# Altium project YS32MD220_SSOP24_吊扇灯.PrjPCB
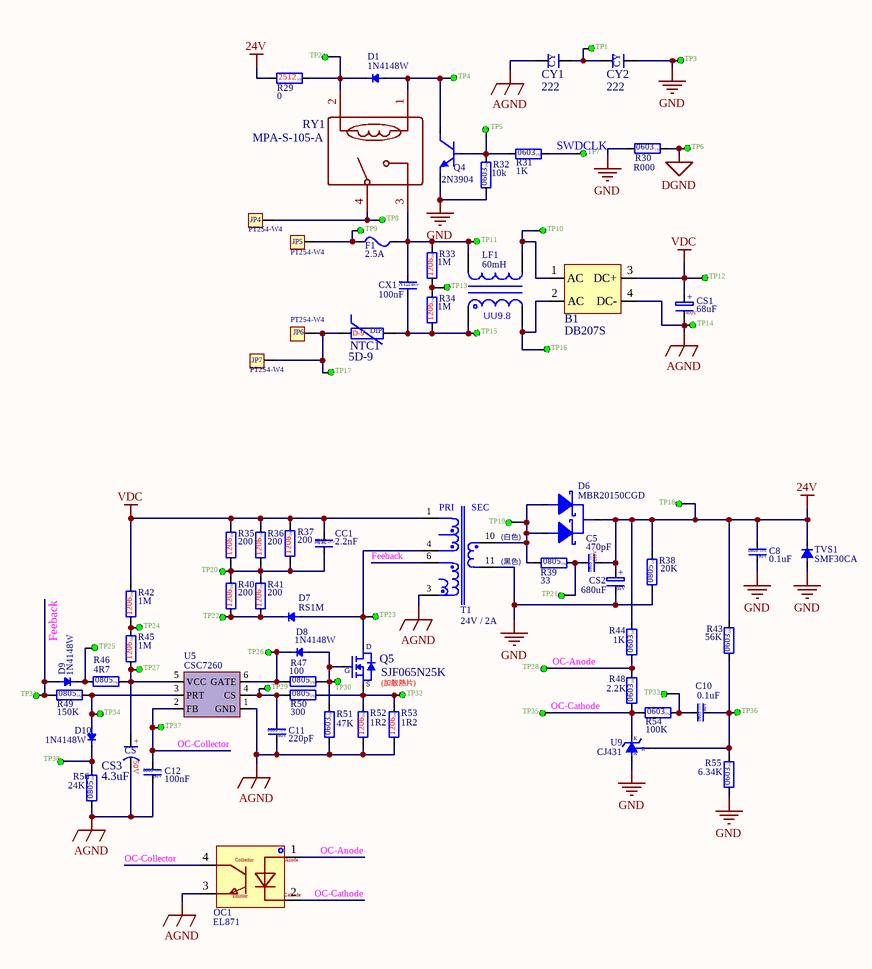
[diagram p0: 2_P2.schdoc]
2 sheets, 168 parts. Net scope: flat (ports and power ports of the same name join across sheets).
Board file: 吊扇灯_DEMO.pcbdoc
Sheets:
  2_P2.schdoc
  1_1.schdoc

## Sheet 2_P2.schdoc
size 307 x 218 mm; Symbol: Drawing-Symbol_A4; Device: Drawing-Symbol_A4; Company: 嘉立创EDA; Version: V1.0; Page Size: A4; @Project Name: YS32MD220_Demo_SSOP24_V1_0; @Page Count: 2; @Update Date: 2025-12-08; @Create Date: 2025-12-08; @Schematic Name: 吊扇灯_DEMO; @Page No: 2; @Page Name: P2; @Board Name: YS32MD220_FAN_LED_Demo_V1_0; @Create Time: 07:20:52; @Update Time: 15:23:17; Title Block Position: 3; Size: A4; Width: 1170; Height: 825; Region Start: 1; X Region Count: 6; Y Region Count: 4; Blade Width: 10

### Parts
B1  DB207S  [DBS]
C5  470pF  [C 0805]
C8  0.1uF  [C 0805]
C10  0.1uF  [C 0603]
C11  220pF  [C 0603]
C12  100nF  [C 0603]
CC1  2.2nF  [CC 5*5]
CS1  68uF  [CAP 7.5*18*35.5 - BK]
CS2  680uF  [CAP 5.0*10*16 - GD]
CS3  4.3uF  [CAP 2.5*5*11 - BK]
CX1  100nF  [CX 10*13*11]
CY1  222  [CY 5*7*2.5]
CY2  222  [CY 5*7*2.5]
D1  1N4148W  [SOD-123]
D6  MBR20150CGD  [TO263-2]
D7  RS1M  [SMA]
D8  1N4148W  [SOD-123]
D9  1N4148W  [SOD-123]
D10  1N4148W  [SOD-123]
F1  2.5A  [FU DIP 8.5X8.5X4]
JP4  PT254-W4  [PT254-W4]
JP5  PT254-W4  [PT254-W4]
JP6  PT254-W4  [PT254-W4]
JP7  PT254-W4  [PT254-W4]
LF1  60mH  [UU9.8]
NTC1  5D-9  [NTC D-9]
OC1  EL871  [DIP-4]
Q4  2N3904  [SOT23-3]
Q5  SJF065N25K  [TO220F-A(Heat sinks)]
R29  0  [R 2512]
R30  R000  [R 0603-HP]
R31  1K  [R 0603]
R32  10k  [R 0603]
R33  1M  [R 1206]
R34  1M  [R 1206]
R35  200  [R 1206]
R36  200  [R 1206]
R37  200  [R 1206]
R38  20K  [R 0805]
R39  33  [R 0805]
R40  200  [R 1206]
R41  200  [R 1206]
R42  1M  [R 1206]
R43  56K  [R 0603]
R44  1K  [R 0603]
R45  1M  [R 1206]
R46  4R7  [R 0805]
R47  100  [R 0805]
R48  2.2K  [R 0603]
R49  150K  [R 0805]
R50  300  [R 0805]
R51  47K  [R 0603]
R52  1R2  [R 1206]
R53  1R2  [R 1206]
R54  100K  [R 0603]
R55  6.34K  [R 0603]
R56  24K  [R 0805]
RY1  MPA-S-105-A  [MPA-S-105-A]
T1  24V / 2A  [ZZ200113]
TP1  TP  [TP_circle_1.0mm]  (value not drawn)
TP2  TP  [TP_circle_1.0mm]  (value not drawn)
TP3  TP  [TP_circle_1.0mm]  (value not drawn)
TP4  TP  [TP_circle_1.0mm]  (value not drawn)
TP5  TP  [TP_circle_1.0mm]  (value not drawn)
TP6  TP  [TP_circle_1.0mm]  (value not drawn)
TP7  TP  [TP_circle_1.0mm]  (value not drawn)
TP8  TP  [TP_circle_1.0mm]  (value not drawn)
TP9  TP  [TP_circle_1.0mm]  (value not drawn)
TP10  TP  [TP_circle_1.0mm]  (value not drawn)
TP11  TP  [TP_circle_1.0mm]  (value not drawn)
TP12  TP  [TP_circle_1.0mm]  (value not drawn)
TP13  TP  [TP_circle_1.0mm]  (value not drawn)
TP14  TP  [TP_circle_1.0mm]  (value not drawn)
TP15  TP  [TP_circle_1.0mm]  (value not drawn)
TP16  TP  [TP_circle_1.0mm]  (value not drawn)
TP17  TP  [TP_circle_1.0mm]  (value not drawn)
TP18  TP  [TP_circle_1.0mm]  (value not drawn)
TP19  TP  [TP_circle_1.0mm]  (value not drawn)
TP20  TP  [TP_circle_1.0mm]  (value not drawn)
TP21  TP  [TP_circle_1.0mm]  (value not drawn)
TP22  TP  [TP_circle_1.0mm]  (value not drawn)
TP23  TP  [TP_circle_1.0mm]  (value not drawn)
TP24  TP  [TP_circle_1.0mm]  (value not drawn)
TP25  TP  [TP_circle_1.0mm]  (value not drawn)
TP26  TP  [TP_circle_1.0mm]  (value not drawn)
TP27  TP  [TP_circle_1.0mm]  (value not drawn)
TP28  TP  [TP_circle_1.0mm]  (value not drawn)
TP29  TP  [TP_circle_1.0mm]  (value not drawn)
TP30  TP  [TP_circle_1.0mm]  (value not drawn)
TP31  TP  [TP_circle_1.0mm]  (value not drawn)
TP32  TP  [TP_circle_1.0mm]  (value not drawn)
TP33  TP  [TP_circle_1.0mm]  (value not drawn)
TP34  TP  [TP_circle_1.0mm]  (value not drawn)
TP35  TP  [TP_circle_1.0mm]  (value not drawn)
TP36  TP  [TP_circle_1.0mm]  (value not drawn)
TP37  TP  [TP_circle_1.0mm]  (value not drawn)
TP38  TP  [TP_circle_1.0mm]  (value not drawn)
TVS1  SMF30CA  [SOD-123]
U5  CSC7260  [SOT23-6]
U9  CJ431  [SOT23-3]

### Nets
24V: C5.2 C8.1 CS2.1 D6.2(K) R29.1 R38.2 R43.2 R44.2 TP18.1 TVS1.2
AGND: B1.4(DC-) C11.2 C12.2 CS1.2 CS3.2(K) CY1.2 OC1.3 R51.1 R52.1 R53.1 R56.1 T1.3 TP14.1 U5.1(GND)
DGND: R30.2 TP6.1
GND: C8.2 CS2.2 CY2.1 Q4.2(E) R30.1 R32.1 R38.1 R55.1 T1.11 TP3.1 TVS1.1 U9.2(A)
VDC: B1.3(DC+) CC1.1 CS1.1 R35.2 R36.2 R37.2 R42.2 T1.1 TP12.1
Feeback: D9.1(A) R49.1 T1.6 TP31.1
OC-Anode: OC1.1 R44.1 R48.2 TP28.1
OC-Cathode: OC1.2 R48.1 R54.1 TP35.1 U9.1(K)
OC-Collector: C12.1 OC1.4 TP37.1 U5.2(FB)
SWDCLK: R31.2 TP7.1
NetB1_1: B1.1(AC) LF1.3 TP10.1
NetB1_2: B1.2(AC) LF1.2 TP16.1
NetC5_1: C5.1 R39.2 TP21.1
NetC10_1: C10.1 R54.2 TP33.1
NetC10_2: C10.2 R43.1 R55.2 TP36.1 U9.3(R)
NetC11_1: C11.1 R50.1 TP29.1 U5.4(CS)
NetCC1_2: CC1.2 R35.1 R36.1 R37.1 R40.2 R41.2 TP20.1
NetCS3_1: CS3.1(A) R45.1 R46.2 TP27.1 U5.5(VCC)
NetCX1_1: CX1.1 LF1.1 NTC1.2 R34.1 TP15.1
NetCX1_2: CX1.2 F1.2 LF1.4 R33.2 RY1.3 TP11.1
NetCY1_1: CY1.1 CY2.2 TP1.1
NetD1_1: D1.1(A) Q4.3(C) RY1.1 TP4.1
NetD1_2: D1.2(K) R29.2 RY1.2 TP2.1
NetD6_1: D6.1(A) D6.3(A) R39.1 T1.10 TP19.1
NetD7_1: D7.1(A) Q5.2(D) T1.4 TP23.1
NetD7_2: D7.2(K) R40.1 R41.1 TP22.1
NetD8_1: D8.1(A) Q5.1(G) R47.2 R51.2 TP30.1
NetD8_2: D8.2(K) R47.1 TP26.1 U5.6(GATE)
NetD9_2: D9.2(K) R46.1 TP25.1
NetD10_1: D10.1(A) R49.2 TP34.1 U5.3(PRT)
NetD10_2: D10.2(K) R56.2 TP38.1
NetF1_1: F1.1 JP5.1(PT254-W4) TP9.1
NetJP4_1: JP4.1(PT254-W4) RY1.4 TP8.1
NetJP6_1: JP6.1(PT254-W4) JP7.1(PT254-W4) NTC1.1 TP17.1
NetQ4_1: Q4.1(B) R31.1 R32.2 TP5.1
NetQ5_3: Q5.3(S) R50.2 R52.2 R53.2 TP32.1
NetR33_1: R33.1 R34.2 TP13.1
NetR42_1: R42.1 R45.2 TP24.1

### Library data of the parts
B1 = DB207S: 1000V/2A整流桥
C5 = C_0805_10%_200V: 電容 0805 10% 200V
C8 = C_0805_10%_50V: 電容 0805 10% 50V
C10-C12 = C_0603_10%_50V: 電容 0603 10% 50V
CC1 = CC_DIP_1KV: 陶瓷電容 DIP IKV 腳距5mm
CS1 = CS_DIP_400V: 電解電容 DIP 400V
CS2 = CS_35V: 電解電容 SMD 35V
CS3 = CS_50V: 直插固态电容
CX1 = CX1_2.5KV: X1電容 ≥2.5KV
CY1 CY2 = CY: 安规Y电容; BOM名称: 高压陶瓷电容，Y电容; 版权归属: 封装库来自淘宝 ID：黄晶宝石
D1 D8-D10 = 1N4148: 开关二极管 1N4148W
D6 = MBR20150CGD: 肖特基二极管
D7 = RS1M: 快恢復二級管 / RS1M
F1 = Fuse: 保險絲
JP4-JP7 = PT254-W4: BOM名称: 电话接口; 版权归属: 封装库来自淘宝 ID：黄晶宝石
LF1 = L-UU 9.8: 共模电感 UU9.8
NTC1 = RT_NTC_D-9: DIP NTC (XD-9); BOM名称: 压敏电阻; 版权归属: 封装库来自淘宝 ID：黄晶宝石
OC1 = EL817: 亿光(EVERLIGHT)
Q4 = 2N3904_SMD: SMD NPN 2N3904; BOM名称: 高频放大-NPN型; 版权归属: 封装库来自淘宝 ID：黄晶宝石; 属性: 40V 1.5A 1W 100MHZ
Q5 = MOS_SJF065N25K(散熱): 無錫商甲導體 / SJF065N25K / 680V 4A / (需要安裝散色片)
R29 = R_2512_5%: 貼片電阻 2512 5% 1w
R30 = R_0603_1%: 貼片電阻 0603 1%
R31 R32 R43 R44 R48 R51 R54 R55 = R_0603_5%: 電阻 0603 5%
R33-R37 R40-R42 R45 R52 R53 = R_1206_5%: 電阻 1206 5%
R38 R39 R46 R47 R49 R50 R56 = R_0805_5%: 電阻 0805 5%
RY1 = MPA-S-105-A: MPA-S-105-A / 5V
T1 = ZZ200113: 廣東中正電子
TP1-TP38 = ICT_TP_1.0mm: ICT測試點 1.0mm
TVS1 = SMF30CA: TVS 30V 4A 200W
U5 = CSC7260_1: 晶源微 PWM IC

## Sheet 1_1.schdoc
size 307 x 218 mm; Symbol: Altium_A2; Device: Altium_A2; SheetNumber: 0; SheetTotal: 0; PageSetup: Record=PageOptions聨CenterHorizontal=True聨CenterVertical=True聨PrintScale=0.73聨XCorrection=1.00聨YCorrection=1.00聨PrintKind=0聨BorderSize=5000000聨LeftOffset=0聨BottomOffset=0聨Orientation=2聨PaperLength=1000聨PaperWidth=1000聨Scale=100聨PaperSource=7聨PrintQuality=-4聨MediaType=1聨DitherType=10聨PaperKind=A3聨PrintScaleMode=1; Width: 1170; Height: 825; X Region Count: 0; Y Region Count: 0; Blade Width: 0; Region Start: 1; Title Block Position: 3; @Page No: 1; @Page Count: 2; @Schematic Name: 吊扇灯_DEMO; @Project Name: 吊扇灯_DEMO_V1; @Board Name: 吊扇灯_DEMO; @Update Date: 2025-12-09; @Create Time: 06:26:14; @Update Time: 13:44:14; @Page Name: 1; @Create Date: 2025-12-05
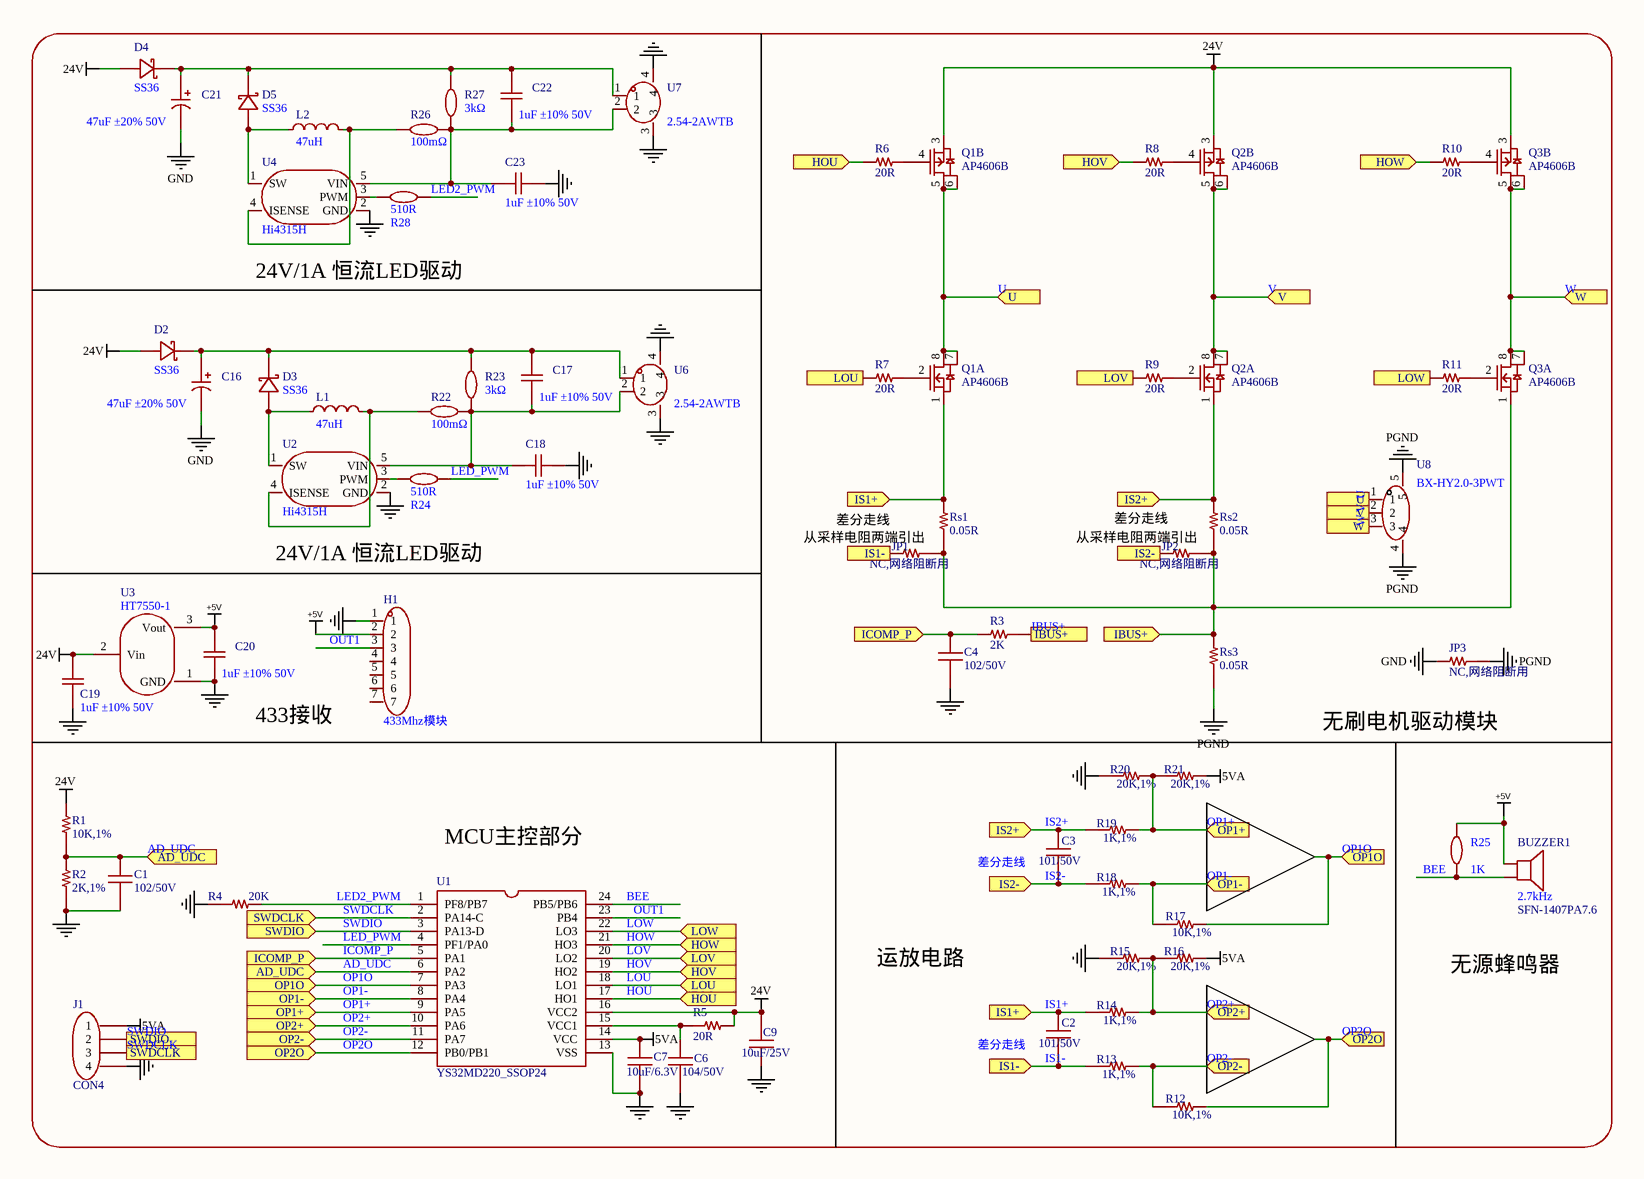
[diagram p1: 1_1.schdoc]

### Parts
BUZZER1  2.7kHz  [BUZ-TH_BD14.0-P7.60-D0.7]
C1  102/50V  [C0603]
C2  101/50V  [C0603]
C3  101/50V  [C0603]
C4  102/50V  [C0603]
C6  104/50V  [C0603]
C7  10uF/6.3V  [C0603]
C9  10uF/25V  [C0805]
C16  47uF ±20% 50V  [CAP-SMD_BD6.3-L6.6-W6.6-FD]
C17  1uF ±10% 50V  [C0603]
C18  1uF ±10% 50V  [C0603]
C19  1uF ±10% 50V  [C0603]
C20  1uF ±10% 50V  [C0603]
C21  47uF ±20% 50V  [CAP-SMD_BD6.3-L6.6-W6.6-FD]
C22  1uF ±10% 50V  [C0603]
C23  1uF ±10% 50V  [C0603]
D2  SS36  [SMA_L4.3-W2.6-LS5.0-FD]
D3  SS36  [SMA_L4.3-W2.6-LS5.0-FD]
D4  SS36  [SMA_L4.3-W2.6-LS5.0-FD]
D5  SS36  [SMA_L4.3-W2.6-LS5.0-FD]
H1  433Mhz模块  [433Mhz]
J1  CON4  [SIP4-2.0]
JP1  NC,网络阻断用  [JP3.0]
JP2  NC,网络阻断用  [JP3.0]
JP3  NC,网络阻断用  [JP3.0]
L1  47uH  [IND-SMD_L12.3-W12.3]
L2  47uH  [IND-SMD_L12.3-W12.3]
Q1  AP4606B  [SOP8]  (parts A,B of 2)
Q2  AP4606B  [SOP8]  (parts A,B of 2)
Q3  AP4606B  [SOP8]  (parts A,B of 2)
R1  10K,1%  [R0603]
R2  2K,1%  [R0603]
R3  2K  [R0603]
R4  20K  [R0603]
R5  20R  [R0603]
R6  20R  [R0603]
R7  20R  [R0603]
R8  20R  [R0603]
R9  20R  [R0603]
R10  20R  [R0603]
R11  20R  [R0603]
R12  10K,1%  [R0603]
R13  1K,1%  [R0603]
R14  1K,1%  [R0603]
R15  20K,1%  [R0603]
R16  20K,1%  [R0603]
R17  10K,1%  [R0603]
R18  1K,1%  [R0603]
R19  1K,1%  [R0603]
R20  20K,1%  [R0603]
R21  20K,1%  [R0603]
R22  100mΩ  [R0805]
R23  3kΩ  [R0805]
R24  510R  [R0603]
R25  1K  [R0603]
R26  100mΩ  [R0805]
R27  3kΩ  [R0805]
R28  510R  [R0603]
Rs1  0.05R  [R1206]
Rs2  0.05R  [R1206]
Rs3  0.05R  [R1206]
U1  YS32MD220_SSOP24  [SSOP-24_L8.7-W3.9-P0.635]
U2  Hi4315H  [SOT-89-5_L4.5-W2.5-P1.50-LS4.5-TL]
U3  HT7550-1  [SOT-89-3_L4.5-W2.5-P1.50-LS4.2-BR]
U4  Hi4315H  [SOT-89-5_L4.5-W2.5-P1.50-LS4.5-TL]
U6  2.54-2AWTB  [CONN-SMD_2P-P2.54_XH2.54-2AWT]
U7  2.54-2AWTB  [CONN-SMD_2P-P2.54_XH2.54-2AWT]
U8  BX-HY2.0-3PWT  [CONN-SMD_3P-P2.0_BX-HY2.0-3PWT]

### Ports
AD_UDC (in), HOU (in), HOV (in), HOW (in), IBUS+ (in), ICOMP_P (in), IS1+ (in), IS1- (in), IS2+ (in), IS2- (in), LOU (in), LOV (in), LOW (in), OP1+ (in), OP1- (in), OP1O (in), OP2+ (in), OP2- (in), OP2O (in), SWDCLK (in), SWDIO (in), U (in), V (in), W (in)

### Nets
5VA: C7.1 J1.1 R16.1 R21.1 U1.14(VCC)
24V: C9.2 C19.2 D2.1(A) D4.1(A) Q1.3(S) Q2.3(S) Q3.3(S) R1.1 R5.1 U1.16(VCC2) U3.2(Vin)
+5V: BUZZER1.1 C20.2 H1.2 R25.2 U3.3(Vout)
GND: C1.2 C4.2 C6.2 C7.2 C9.1 C16.2 C18.1 C19.1 C20.1 C21.2 C23.1 H1.1 J1.4 JP3.1 R2.2 R4.2 R15.2 R20.2 U1.13(VSS) U2.2(GND) U3.1(GND) U4.2(GND) U6.3 U6.4 U7.3 U7.4
PGND: JP3.2 Rs3.2 U8.4 U8.5
AD_UDC: C1.1 R1.2 R2.1 U1.6(PA2) ; port AD_UDC
BEE: BUZZER1.2 R25.1 U1.24(PB5/PB6)
HOU: R6.1 U1.17(HO1) ; port HOU
HOV: R8.1 U1.19(HO2) ; port HOV
HOW: R10.1 U1.21(HO3) ; port HOW
IBUS+: JP1.2 JP2.2 Q3.1(G) R3.2 Rs1.2 Rs2.2 Rs3.1 ; port IBUS+
ICOMP_P: C4.1 R3.1 U1.5(PA1) ; port ICOMP_P
IS1+: C2.1 Q1.1(G) R14.2 Rs1.1 ; port IS1+
IS1-: C2.2 JP1.1 R13.2 ; port IS1-
IS2+: C3.1 Q2.1(G) R19.2 Rs2.1 ; port IS2+
IS2-: C3.2 JP2.1 R18.2 ; port IS2-
LED2_PWM: R4.1 R28.2 U1.1(PF8/PB7)
LED_PWM: R24.2 U1.4(PF1/PA0)
LOU: R7.1 U1.18(LO1) ; port LOU
LOV: R9.1 U1.20(LO2) ; port LOV
LOW: R11.1 U1.22(LO3) ; port LOW
OP1+: R19.1 R20.1 R21.2 U1.9(PA5) ; port OP1+
OP1-: R17.2 R18.1 U1.8(PA4) ; port OP1-
OP1O: R17.1 U1.7(PA3) ; port OP1O
OP2+: R14.1 R15.1 R16.2 U1.10(PA6) ; port OP2+
OP2-: R12.2 R13.1 U1.11(PA7) ; port OP2-
OP2O: R12.1 U1.12(PB0/PB1) ; port OP2O
OUT1: H1.3 U1.23(PB4)
SWDCLK: J1.3 U1.2(PA14-C) ; port SWDCLK
SWDIO: J1.2 U1.3(PA13-D) ; port SWDIO
U: Q1.5(D) Q1.6(D) Q1.7(D) Q1.8(D) U8.1 ; port U
V: Q2.5(D) Q2.6(D) Q2.7(D) Q2.8(D) U8.2 ; port V
W: Q3.5(D) Q3.6(D) Q3.7(D) Q3.8(D) U8.3 ; port W
NetC6_1: C6.1 R5.2 U1.15(VCC1)
NetC16_1: C16.1 C17.2 D2.2(K) D3.2(K) R23.2 U6.1
NetC17_1: C17.1 C18.2 R22.2 R23.1 U2.5(VIN) U6.2
NetC21_1: C21.1 C22.2 D4.2(K) D5.2(K) R27.2 U7.1
NetC22_1: C22.1 C23.2 R26.2 R27.1 U4.5(VIN) U7.2
NetD3_1: D3.1(A) L1.1 U2.1(SW)
NetD5_1: D5.1(A) L2.1 U4.1(SW)
NetL1_2: L1.2 R22.1 U2.4(ISENSE)
NetL2_2: L2.2 R26.1 U4.4(ISENSE)
NetQ1_2: Q1.2(S) R7.2
NetQ1_4: Q1.4(G) R6.2
NetQ2_2: Q2.2(S) R9.2
NetQ2_4: Q2.4(G) R8.2
NetQ3_2: Q3.2(S) R11.2
NetQ3_4: Q3.4(G) R10.2
NetR24_1: R24.1 U2.3(PWM)
NetR28_1: R28.1 U4.3(PWM)

Not connected (* = marked no-connect by the designer): H1 4 5 6 7

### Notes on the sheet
- 24V/1A 恒流LED驱动
- (near JP1) 差分走线
- (near JP2) 差分走线
- (near JP1) 从采样电阻两端引出
- (near JP2) 从采样电阻两端引出
- 433接收
- 无刷电机驱动模块
- MCU主控部分
- 差分走线
- 运放电路
- 无源蜂鸣器

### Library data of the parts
BUZZER1 = SFN-1407PA7.6: Manufacturer: S&S(海旭); Add into BOM: yes; Driver Circuitry: 无源(外部驱动); Sound Pressure Level(SPL): 85dB
C1 C4 = 102/50V: Symbol: CAP; Origin Footprint 2: C0805; Origin Footprint 3: C1206; Origin Footprint 4: C0402; Add into BOM: yes
C2 C3 = 101/50V: Symbol: CAP; Origin Footprint 2: C0805; Origin Footprint 3: C1206; Origin Footprint 4: C0402; Add into BOM: yes
C6 = 104/50V: Symbol: CAP; Origin Footprint 2: C0805; Origin Footprint 3: C1206; Origin Footprint 4: C0402; Origin Footprint 5: 0603; Add into BOM: yes
C7 = 10uF/6.3V: Symbol: CAP; Origin Footprint 2: C0805; Origin Footprint 3: C1206; Origin Footprint 4: C0402; Add into BOM: yes
C9 = 10uF/25V: Symbol: CAP; Origin Footprint 2: C0603; Origin Footprint 3: C1206; Origin Footprint 4: C0402; Add into BOM: yes
C16 C21 = JVJ50V47M6x8: Manufacturer: JIERR(捷而瑞); Add into BOM: yes; Ripple Current: 63mA@120Hz; Lifetime: 2000hrs@105℃
C17-C20 C22 C23 = CL10A105KB8NNNC: Manufacturer: SAMSUNG(三星); Add into BOM: yes; Temperature Coefficient: X5R
D2-D5 = SS36_C7420367: Manufacturer: R+O(宏嘉诚); Add into BOM: yes; Diode Configuration: 独立式; Voltage - Forward(Vf@If): 700mV@3.0A; Voltage - DC Reverse(Vr): 60V; Current - Rectified: 3A; Reverse Leakage Current (Ir): 10mA@60V; Operating Junction Temperature Range: -55℃~+150℃; Non-Repetitive Peak Forward Surge Current: 80A
H1 = PM254V-11-07-H85: Manufacturer: XFCN(兴飞); Add into BOM: yes
J1 = CON4: Origin Footprint 2: SIP4; Add into BOM: yes
JP1 JP2 = NC,网络阻断用: Symbol: RES; Origin Footprint 2: R0402; Origin Footprint 3: R0603; Origin Footprint 4: R0805; Origin Footprint 5: R1206; Origin Footprint 6: R2010; Origin Footprint 7: R2512; Add into BOM: yes; Origin Footprint 1: JP1.0
JP3 = NC,网络阻断用: Symbol: RES; Origin Footprint 2: R0402; Origin Footprint 3: R0603; Origin Footprint 4: R0805; Origin Footprint 5: R1206; Origin Footprint 6: R2010; Origin Footprint 7: R2512; Add into BOM: yes
L1 L2 = SMDRI127-470MT: Manufacturer: SXN(顺翔诺); Add into BOM: yes; Tolerance: ±20%; Current Rating: 2.5A; Current - Saturation(Isat): 4.6A; DC Resistance(DCR): 100mΩ; Type: 屏蔽电感
Q1-Q3 = AP4606B: Symbol: MOS-PN-8; Origin Footprint 2: DFN3x3D; Origin Footprint 3: DFN5X6D; Add into BOM: yes
R1 R12 R17 = 10K,1%: Symbol: RES; Origin Footprint 2: R0402; Origin Footprint 3: R0805; Origin Footprint 4: R1206; Origin Footprint 5: R2010; Origin Footprint 6: R2512; Add into BOM: yes
R2 = 2K,1%: Symbol: RES; Origin Footprint 2: R0402; Origin Footprint 3: R0805; Origin Footprint 4: R1206; Origin Footprint 5: R2010; Origin Footprint 6: R2512; Add into BOM: yes
R3 = 2K: Symbol: RES; Origin Footprint 2: R0402; Origin Footprint 3: R0805; Origin Footprint 4: R1206; Origin Footprint 5: R2010; Origin Footprint 6: R2512; Add into BOM: yes
R4 = 20K: Symbol: RES; Origin Footprint 2: R0402; Origin Footprint 3: R0805; Origin Footprint 4: R1206; Origin Footprint 5: R2010; Origin Footprint 6: R2512; Add into BOM: yes
R5-R11 = 20R: Symbol: RES; Origin Footprint 2: R0402; Origin Footprint 3: R0805; Origin Footprint 4: R1206; Origin Footprint 5: R2010; Origin Footprint 6: R2512; Add into BOM: yes
R13 R14 R18 R19 = 1K,1%: Symbol: RES; Origin Footprint 2: R0402; Origin Footprint 3: R0805; Origin Footprint 4: R1206; Origin Footprint 5: R2010; Origin Footprint 6: R2512; Add into BOM: yes
R15 R16 R20 R21 = 20K,1%: Symbol: RES; Origin Footprint 2: R0402; Origin Footprint 3: R0805; Origin Footprint 4: R1206; Origin Footprint 5: R2010; Origin Footprint 6: R2512; Add into BOM: yes
R22 R26 = 0805W8F100LT5E: Manufacturer: UNI-ROYAL(厚声); Add into BOM: yes; Tolerance: ±1%; Power(Watts): 125mW; Voltage-Supply(Max): 150V; Temperature Coefficient: ±800ppm/℃
R23 R27 = 0805W8F3001T5E: Manufacturer: UNI-ROYAL(厚声); Add into BOM: yes; Tolerance: ±1%; Power(Watts): 125mW; Voltage-Supply(Max): 150V; Temperature Coefficient: ±100ppm/℃
R24 R25 R28 = Res_0603: Symbol: 电阻; Convert to PCB: yes
Rs1-Rs3 = 0.05R: Symbol: RES; Origin Footprint 2: R0402; Origin Footprint 3: R0603; Origin Footprint 4: R0805; Origin Footprint 5: R1206S; Origin Footprint 6: R2010; Origin Footprint 7: R2512; Add into BOM: yes
U1 = YS32MD220_SSOP24: Add into BOM: yes
U2 U4 = Hi4315H: Manufacturer: Hichips(智芯); Add into BOM: yes; Voltage - Input: 5V~60V; Frequency - Switching: 1MHz; Number of Channels: 1; Output Current: 1.5A; Dimming: PWM; Topology: 降压
U3 = HT7550-1_C16106: Manufacturer: HOLTEK(合泰/盛群); Add into BOM: yes; Output Type: 固定; Voltage - Supply: 30V; Output Voltage: 5V; Output Current: 150mA; Voltage Dropout: 25mV@(1mA); standby current: 2.5uA; Output Configuration: 正极; Number of Outputs: 1
U6 U7 = 2.54-2AWTB: Manufacturer: CAX(创都); Add into BOM: yes; Pins Structure: 1x2P; Pitch: 2.54mm; Number of PINs Per Row: 2; Current Rating: 3A; Voltage Rating: 250V; Plastic Material: LCP; Y-Width of Bottom Edge on Board: 6mm
U8 = BX-HY2.0-3PWT: Manufacturer: Bossie(博锡); Add into BOM: yes; Pins Structure: 1x3P; Pitch: 2mm; Reference Series: HY; Number of PINs Per Row: 3; Current Rating: 2A; Supplementary Features: 辅助焊脚; Z-Height of the Board: 5.2mm; X-Length of Bottom Edge on Board (Spacing Line): 10mm; Y-Width of Bottom Edge on Board: 10.5mm

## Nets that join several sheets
24V: 2_P2 (10 pins), 1_1 (11 pins)
GND: 2_P2 (12 pins), 1_1 (26 pins)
